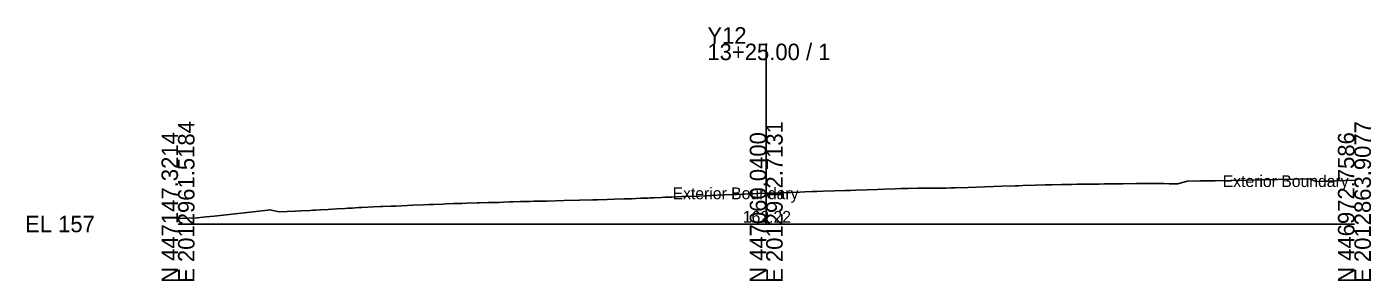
# Model space of a CAD drawing. Extents: x -26 to 1203, y -10 to 9542.
# Drawn here: x -25.7 to 202.8, y 6490.3 to 6533.5 of the extents above; entities that cross this region are included whole.
import ezdxf

# ---------------------------------------------------------------- set-up
doc = ezdxf.new("R2010")
doc.units = 0
for name, color, linetype in [('Default', 7, 'Continuous'), ('Exist Cross Section Cell', 7, 'Continuous'), ('Exist XS Center Line Elevation Label', 7, 'Continuous'), ('Exist XS Ground Line', 7, 'Continuous'), ('Scratch_Level_0', 7, 'Continuous')]:
    doc.layers.add(name, color=color, linetype=linetype)

msp = doc.modelspace()

# ---------------------------------------------------------------- linework, layer by layer
at = {"layer": 'Exist Cross Section Cell'}
for p, q in [((100, 6500), (100, 6530.64)), ((0, 6500), (100, 6500)), ((100, 6500), (200, 6500))]:
    msp.add_line(p, q, dxfattribs=at)
at = {"layer": 'Exist XS Ground Line'}
msp.add_lwpolyline([(0, 6500.96), (1.78, 6501.02), (3.24, 6501.08), (4.81, 6501.21), (6.16, 6501.32), (13.26, 6502.11), (15.26, 6502.38), (15.62, 6502.43), (17.22, 6502.05), (19.91, 6502.19), (20.94, 6502.24), (22.55, 6502.32), (22.93, 6502.34), (23.39, 6502.37), (24.3, 6502.41), (25.55, 6502.48), (27.02, 6502.57), (28.39, 6502.64), (28.85, 6502.67), (29.67, 6502.72), (30.69, 6502.79), (31.25, 6502.81), (33.26, 6502.91), (34.36, 6502.95), (34.8, 6502.97), (36.2, 6503.02), (36.98, 6503.06), (38.03, 6503.11), (39.92, 6503.18), (41.71, 6503.26), (42.7, 6503.29), (43.49, 6503.33), (45.05, 6503.39), (45.56, 6503.41), (46.83, 6503.46), (47.63, 6503.49), (48.24, 6503.51), (49.02, 6503.53), (50.86, 6503.59), (51.27, 6503.6), (52.73, 6503.64), (54.14, 6503.67), (54.57, 6503.68), (55.34, 6503.72), (56.4, 6503.76), (57, 6503.78), (58.24, 6503.81), (59.86, 6503.85), (60.48, 6503.86), (62.71, 6503.91), (65.59, 6504), (68.27, 6504.07), (70.53, 6504.1), (71.3, 6504.12), (72.94, 6504.17), (74.2, 6504.21), (75.86, 6504.26), (77.07, 6504.3), (78.69, 6504.37), (79.94, 6504.42), (80.28, 6504.43), (80.9, 6504.46), (82.13, 6504.51), (82.8, 6504.54), (83.98, 6504.59), (85.67, 6504.65), (86.09, 6504.66), (88.53, 6504.75), (91.58, 6504.88), (94.23, 6504.99), (94.97, 6505.02), (96.27, 6505.08), (97.09, 6505.12), (98.63, 6505.19), (100, 6505.22), (101.39, 6505.27), (102.3, 6505.3), (102.81, 6505.32), (104.16, 6505.37), (105.69, 6505.42), (106.57, 6505.46), (107.84, 6505.5), (108.58, 6505.53), (109.69, 6505.57), (111.68, 6505.64), (113.37, 6505.69), (114.32, 6505.71), (115.22, 6505.74), (117.17, 6505.81), (118.89, 6505.86), (120.03, 6505.9), (121.91, 6505.97), (122.88, 6506.01), (124.11, 6506.03), (125.73, 6506.07), (127.02, 6506.08), (128.03, 6506.09), (128.59, 6506.1), (130.58, 6506.12), (131.46, 6506.13), (132.15, 6506.14), (134.33, 6506.18), (137.23, 6506.31), (140.06, 6506.41), (142.35, 6506.48), (142.91, 6506.5), (143.61, 6506.52), (145.78, 6506.59), (147.45, 6506.65), (148.63, 6506.68), (150.19, 6506.71), (151.55, 6506.73), (151.92, 6506.74), (152.82, 6506.75), (154.63, 6506.78), (156.6, 6506.8), (157.44, 6506.82), (157.81, 6506.82), (160.12, 6506.85), (160.68, 6506.85), (162.95, 6506.88), (164.26, 6506.89), (165.3, 6506.88), (167.54, 6506.86), (168.52, 6506.85), (169.98, 6506.83), (170.55, 6507), (171.6, 6507.3), (173.79, 6507.31), (176.34, 6507.32), (192.4, 6507.68), (193.49, 6507.21), (194.83, 6507.26), (195.56, 6507.29), (196.78, 6507.33), (200, 6507.44)], dxfattribs=at)

# ---------------------------------------------------------------- texts
at = {"layer": 'Default'}
msp.add_text('-', height=0.0001, dxfattribs=at).set_placement((0, 6500))
at = {"layer": 'Exist Cross Section Cell'}
for s, p in [('Y12', (90, 6530.64)), ('13+25.00 / 1', (90, 6527.84)), ('EL 157', (-26, 6498.6))]:
    msp.add_text(s, height=2.8, dxfattribs=at).set_placement(p)
for s, p in [('N 447147.3214', (0, 6490)), ('E 2012961.5184', (2.8, 6490)), ('E 2012912.7131', (102.8, 6490)), ('E 2012863.9077', (202.8, 6490)), ('N 447060.0400', (100, 6490)), ('N 446972.7586', (200, 6490))]:
    msp.add_text(s, height=2.8, rotation=90, dxfattribs=at).set_placement(p)
at = {"layer": 'Exist XS Center Line Elevation Label'}
msp.add_text('162.22', height=2, dxfattribs=at).set_placement((96.03, 6500.22))
at = {"layer": 'Scratch_Level_0'}
for p in [(177.61, 6506.29), (84.08, 6504.21)]:
    msp.add_text('Exterior Boundary', height=2, dxfattribs=at).set_placement(p)

doc.saveas('drawing.dxf')
